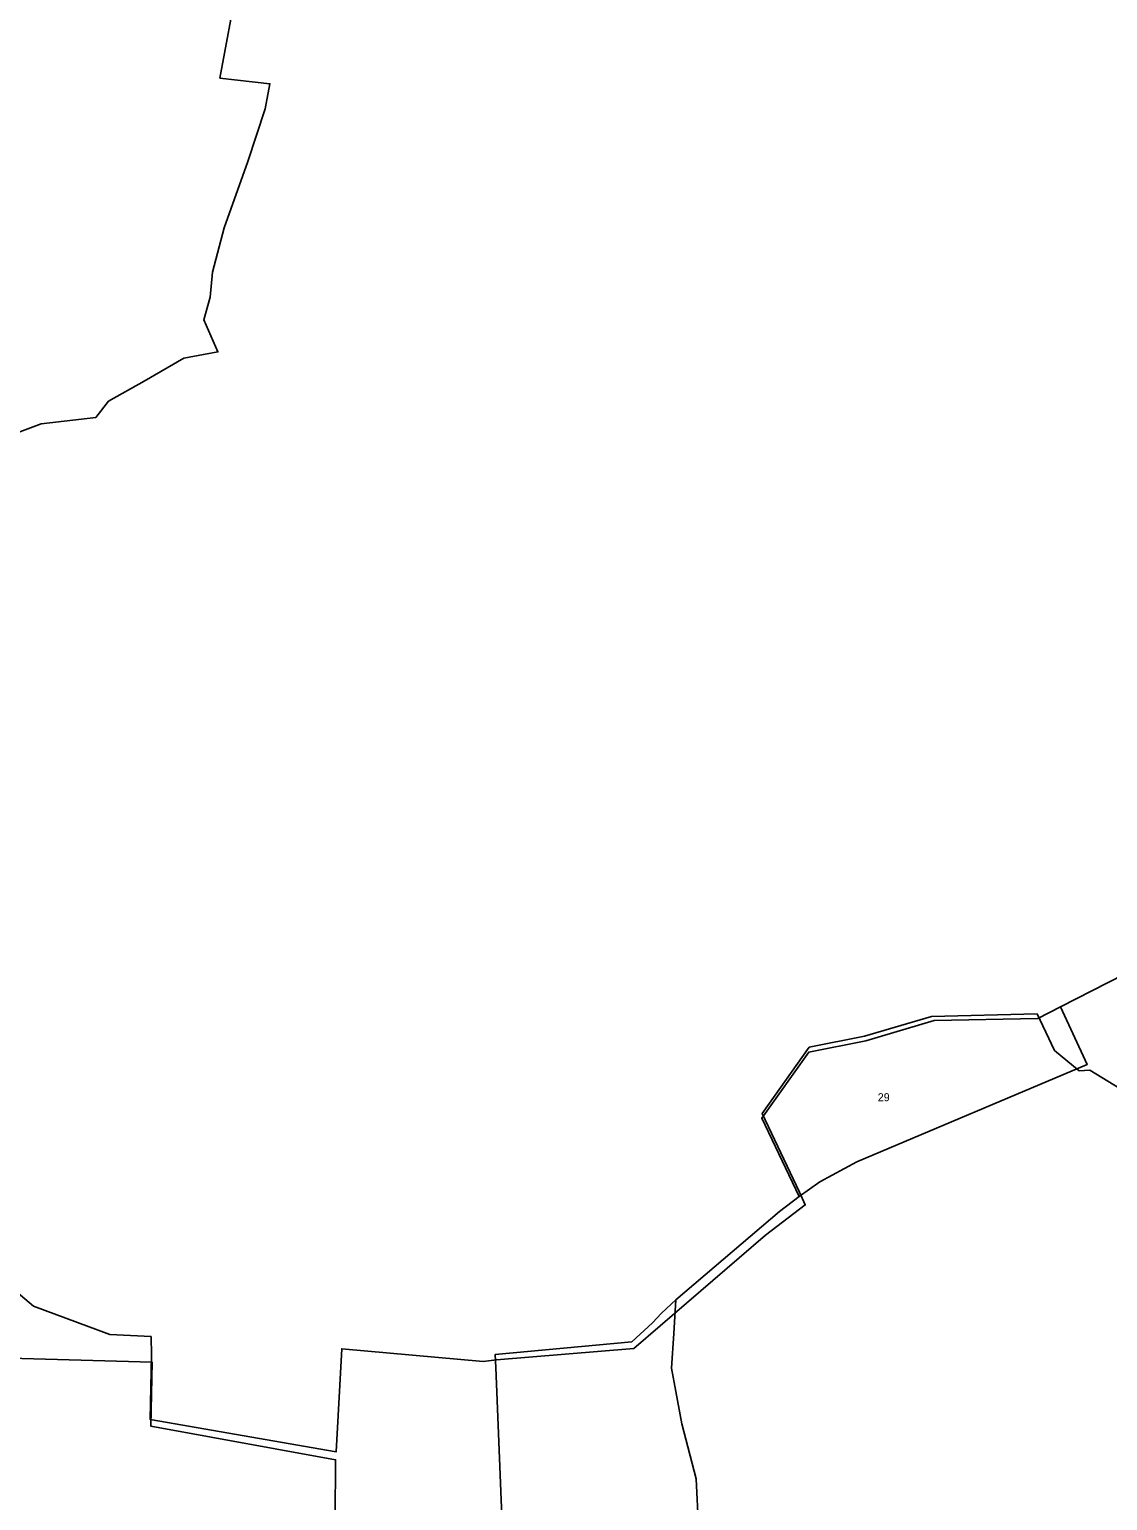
# Model space of a CAD drawing. Extents: x -521621 to -516761, y -1190184 to -1184927.
# Drawn here: x -519813 to -519274, y -1186738 to -1186003 of the extents above; entities that cross this region are included whole.
import ezdxf

# ---------------------------------------------------------------- set-up
doc = ezdxf.new("R2010")
doc.units = 0
doc.layers.add('BPEJ_s', color=7, linetype='Continuous')
doc.layers.add('odvodneni_s', color=7, linetype='Continuous')

msp = doc.modelspace()

# ---------------------------------------------------------------- linework, layer by layer
at = {"layer": 'BPEJ_s'}
for points in [[(-519835.91, -1185986.97), (-519743.68, -1185975.43), (-519719.26, -1185978.21), (-519708.77, -1185979.41), (-519717.55, -1186026.86), (-519692.52, -1186029.68), (-519694.94, -1186042.2), (-519703.63, -1186068.57), (-519715.41, -1186101.68), (-519721.29, -1186123.84), (-519722.41, -1186136.46), (-519725.5, -1186147.69), (-519718.51, -1186163.72), (-519735.51, -1186166.9), (-519755.41, -1186178.34), (-519773.17, -1186188.36), (-519779.59, -1186196.53), (-519806.91, -1186199.69), (-519830.49, -1186208.54)], [(-519830.49, -1186208.54), (-519806.91, -1186199.69), (-519779.59, -1186196.53), (-519773.17, -1186188.36), (-519755.41, -1186178.34), (-519735.51, -1186166.9), (-519718.51, -1186163.72), (-519725.5, -1186147.69), (-519722.41, -1186136.46), (-519721.29, -1186123.84), (-519715.41, -1186101.68), (-519703.63, -1186068.57), (-519694.94, -1186042.2), (-519692.52, -1186029.68), (-519717.55, -1186026.86), (-519708.77, -1185979.41)], [(-519218.04, -1186450.6), (-519297.4, -1186491.12), (-519308.81, -1186496.83), (-519360.57, -1186497.94), (-519394.66, -1186508.1), (-519423.19, -1186513.67), (-519446.7, -1186546.72), (-519428.09, -1186585.87), (-519437.8, -1186593.43), (-519489.59, -1186637.44), (-519496.75, -1186644.17), (-519501.39, -1186648.96), (-519511.68, -1186658.53), (-519579.94, -1186664.8), (-519579.64, -1186671.38), (-519573.71, -1186819.93)], [(-519478.28, -1186750.89), (-519479.52, -1186727.04), (-519486.64, -1186699.48), (-519489.73, -1186683.38), (-519491.9, -1186671.61), (-519490.66, -1186654.27), (-519489.59, -1186637.44), (-519437.8, -1186593.43), (-519428.09, -1186585.87), (-519417.63, -1186578.54), (-519399.26, -1186568.61), (-519284.1, -1186519.9), (-519297.4, -1186491.12), (-519218.04, -1186450.6)], [(-519573.71, -1186819.93), (-519579.64, -1186671.38), (-519579.94, -1186664.8), (-519511.68, -1186658.53), (-519501.39, -1186648.96), (-519496.75, -1186644.17), (-519489.59, -1186637.44), (-519490.66, -1186654.27), (-519491.9, -1186671.61), (-519489.73, -1186683.38), (-519486.64, -1186699.48), (-519479.52, -1186727.04), (-519478.28, -1186750.89)], [(-519828.47, -1186666.52), (-519751.33, -1186668.69), (-519752.05, -1186700.7), (-519659.75, -1186717.42), (-519660.24, -1186805.39)], [(-519660.24, -1186805.39), (-519659.75, -1186717.42), (-519752.05, -1186700.7), (-519751.33, -1186668.69), (-519828.47, -1186666.52)]]:
    msp.add_lwpolyline(points, dxfattribs=at)
msp.add_lwpolyline([(-519428.09, -1186585.87), (-519446.7, -1186546.72), (-519423.19, -1186513.67), (-519394.66, -1186508.1), (-519360.57, -1186497.94), (-519308.81, -1186496.83), (-519297.4, -1186491.12), (-519284.1, -1186519.9), (-519399.26, -1186568.61), (-519417.63, -1186578.54)], close=True, dxfattribs=at)
at = {"layer": 'odvodneni_s'}
msp.add_lwpolyline([(-519824.93, -1186628.66), (-519810.64, -1186640.61), (-519772.6, -1186654.91), (-519751.93, -1186655.88), (-519751.71, -1186665.19), (-519752.33, -1186697.34), (-519659.38, -1186713.47), (-519656.68, -1186661.93), (-519585.89, -1186668.25), (-519579.3, -1186667.47), (-519510.6, -1186661.84), (-519444.92, -1186605.18), (-519424.94, -1186590.05), (-519427.77, -1186583.63), (-519446.56, -1186544.32), (-519422.97, -1186511.24), (-519395.3, -1186505.72), (-519361.81, -1186495.82), (-519309.12, -1186494.49), (-519300.33, -1186512.97), (-519288.1, -1186523.04), (-519282.73, -1186522.69), (-519253.62, -1186540.63)], dxfattribs=at)

# ---------------------------------------------------------------- texts
at = {"layer": 'BPEJ_s'}
msp.add_text('29', height=4, dxfattribs=at).set_placement((-519388.73, -1186538.25))

doc.saveas('drawing.dxf')
